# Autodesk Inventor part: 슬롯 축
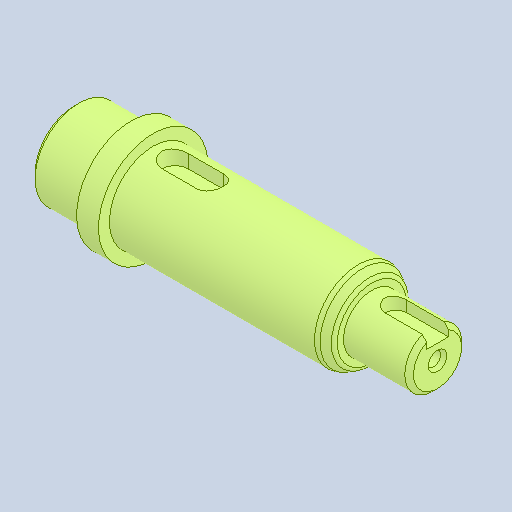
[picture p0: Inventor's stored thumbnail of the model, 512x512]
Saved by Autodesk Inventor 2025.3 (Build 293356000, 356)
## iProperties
Created: 2025-09
Part Number: 슬롯 축
Material: 강철, 탄소
Document SubType Name: Modeling
Designer: PC-15
Density: 7.85 g/cm^3
Appearance: 기본값
Author: jhkim
Sending System: Autodesk Inventor 2026
Preprocessor: ST-DEVELOPER v20.1
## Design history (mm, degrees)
feature "솔리드1"
node "솔리드2"
